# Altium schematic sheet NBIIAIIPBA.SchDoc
size A4; Author: HOWELL
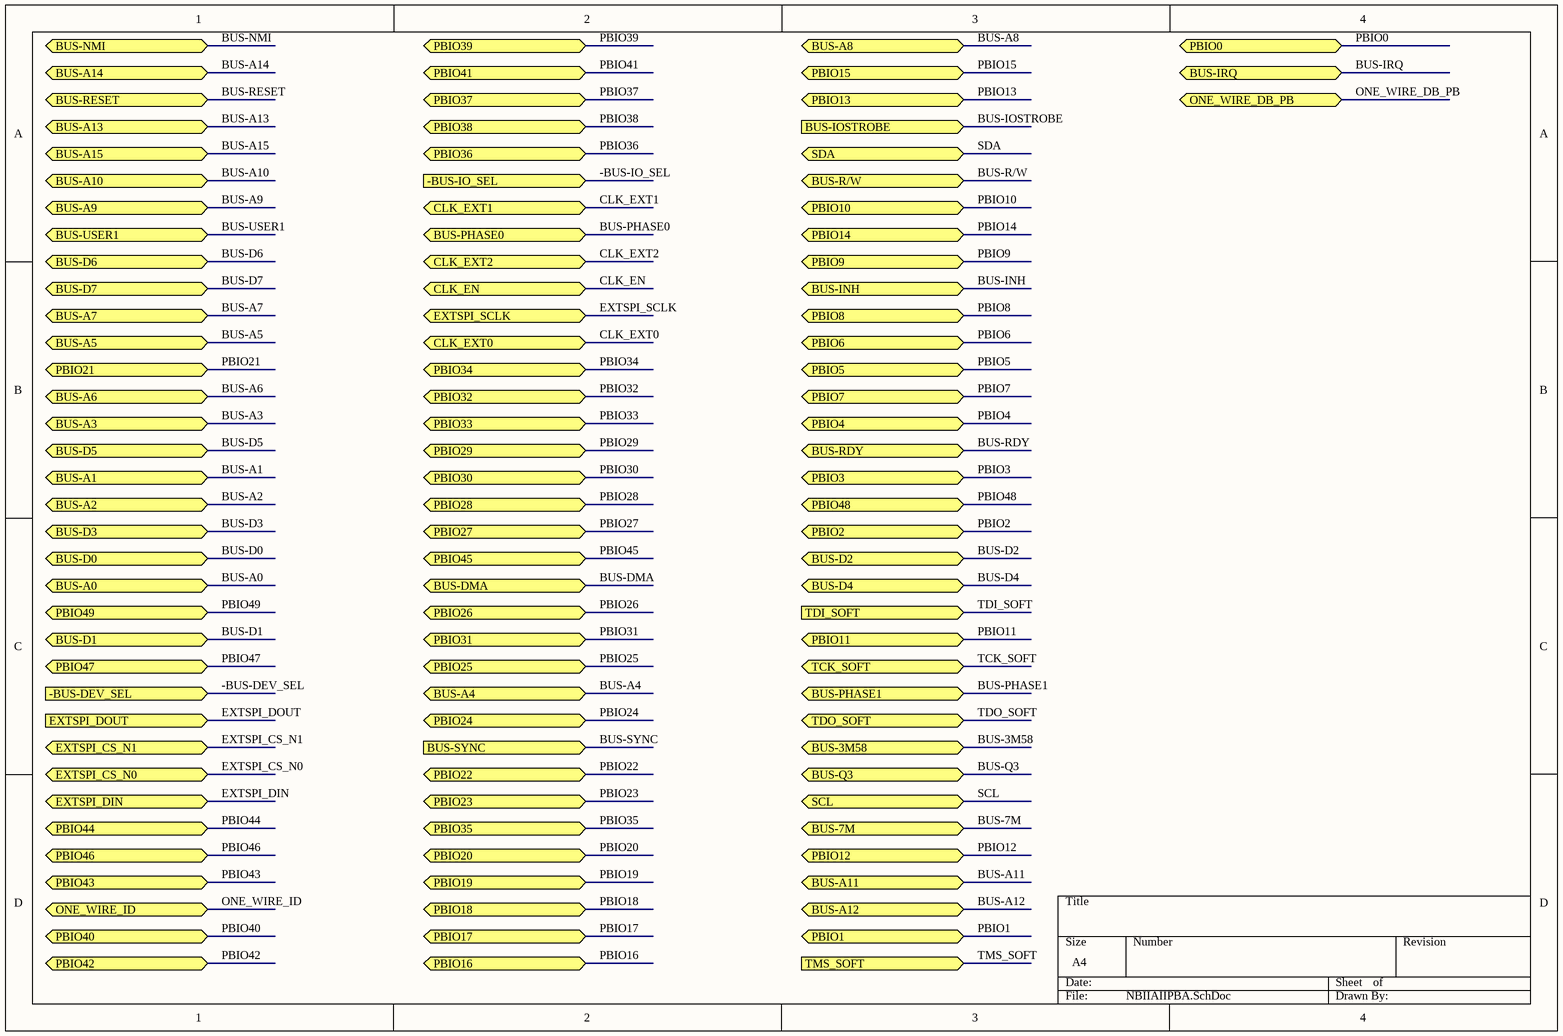
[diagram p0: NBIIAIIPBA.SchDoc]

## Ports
-BUS-DEV_SEL (in), -BUS-IO_SEL (in), BUS-3M58 (bidir), BUS-7M (bidir), BUS-A0 (bidir), BUS-A1 (bidir), BUS-A2 (bidir), BUS-A3 (bidir), BUS-A4 (bidir), BUS-A5 (bidir), BUS-A6 (bidir), BUS-A7 (bidir), BUS-A8 (bidir), BUS-A9 (bidir), BUS-A10 (bidir), BUS-A11 (bidir), BUS-A12 (bidir), BUS-A13 (bidir), BUS-A14 (bidir), BUS-A15 (bidir), BUS-D0 (bidir), BUS-D1 (bidir), BUS-D2 (bidir), BUS-D3 (bidir), BUS-D4 (bidir), BUS-D5 (bidir), BUS-D6 (bidir), BUS-D7 (bidir), BUS-DMA (bidir), BUS-INH (bidir), BUS-IOSTROBE (in), BUS-IRQ (bidir), BUS-NMI (bidir), BUS-PHASE0 (bidir), BUS-PHASE1 (bidir), BUS-Q3 (bidir), BUS-R/W (bidir), BUS-RDY (bidir), BUS-RESET (bidir), BUS-SYNC (in), BUS-USER1 (bidir), CLK_EN (bidir), CLK_EXT0 (bidir), CLK_EXT1 (bidir), CLK_EXT2 (bidir), EXTSPI_CS_N0 (bidir), EXTSPI_CS_N1 (bidir), EXTSPI_DIN (bidir), EXTSPI_DOUT (in), EXTSPI_SCLK (bidir), ONE_WIRE_DB_PB (bidir), ONE_WIRE_ID (bidir), PBIO0 (bidir), PBIO1 (bidir), PBIO2 (bidir), PBIO3 (bidir), PBIO4 (bidir), PBIO5 (bidir), PBIO6 (bidir), PBIO7 (bidir), PBIO8 (bidir), PBIO9 (bidir), PBIO10 (bidir), PBIO11 (bidir), PBIO12 (bidir), PBIO13 (bidir), PBIO14 (bidir), PBIO15 (bidir), PBIO16 (bidir), PBIO17 (bidir), PBIO18 (bidir), PBIO19 (bidir), PBIO20 (bidir), PBIO21 (bidir), PBIO22 (bidir), PBIO23 (bidir), PBIO24 (bidir), PBIO25 (bidir), PBIO26 (bidir), PBIO27 (bidir), PBIO28 (bidir), PBIO29 (bidir), PBIO30 (bidir), PBIO31 (bidir), PBIO32 (bidir), PBIO33 (bidir), PBIO34 (bidir), PBIO35 (bidir), PBIO36 (bidir), PBIO37 (bidir), PBIO38 (bidir), PBIO39 (bidir), PBIO40 (bidir), PBIO41 (bidir), PBIO42 (bidir), PBIO43 (bidir), PBIO44 (bidir), PBIO45 (bidir), PBIO46 (bidir), PBIO47 (bidir), PBIO48 (bidir), PBIO49 (bidir), SCL (bidir), SDA (bidir), TCK_SOFT (bidir), TDI_SOFT (in), TDO_SOFT (bidir), TMS_SOFT (in)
